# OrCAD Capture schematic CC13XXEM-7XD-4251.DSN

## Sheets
1 CC13xxEM-7XD-4251: size A3; title: CC13xxEM-7XD-4251, main; rev: 1.1.0
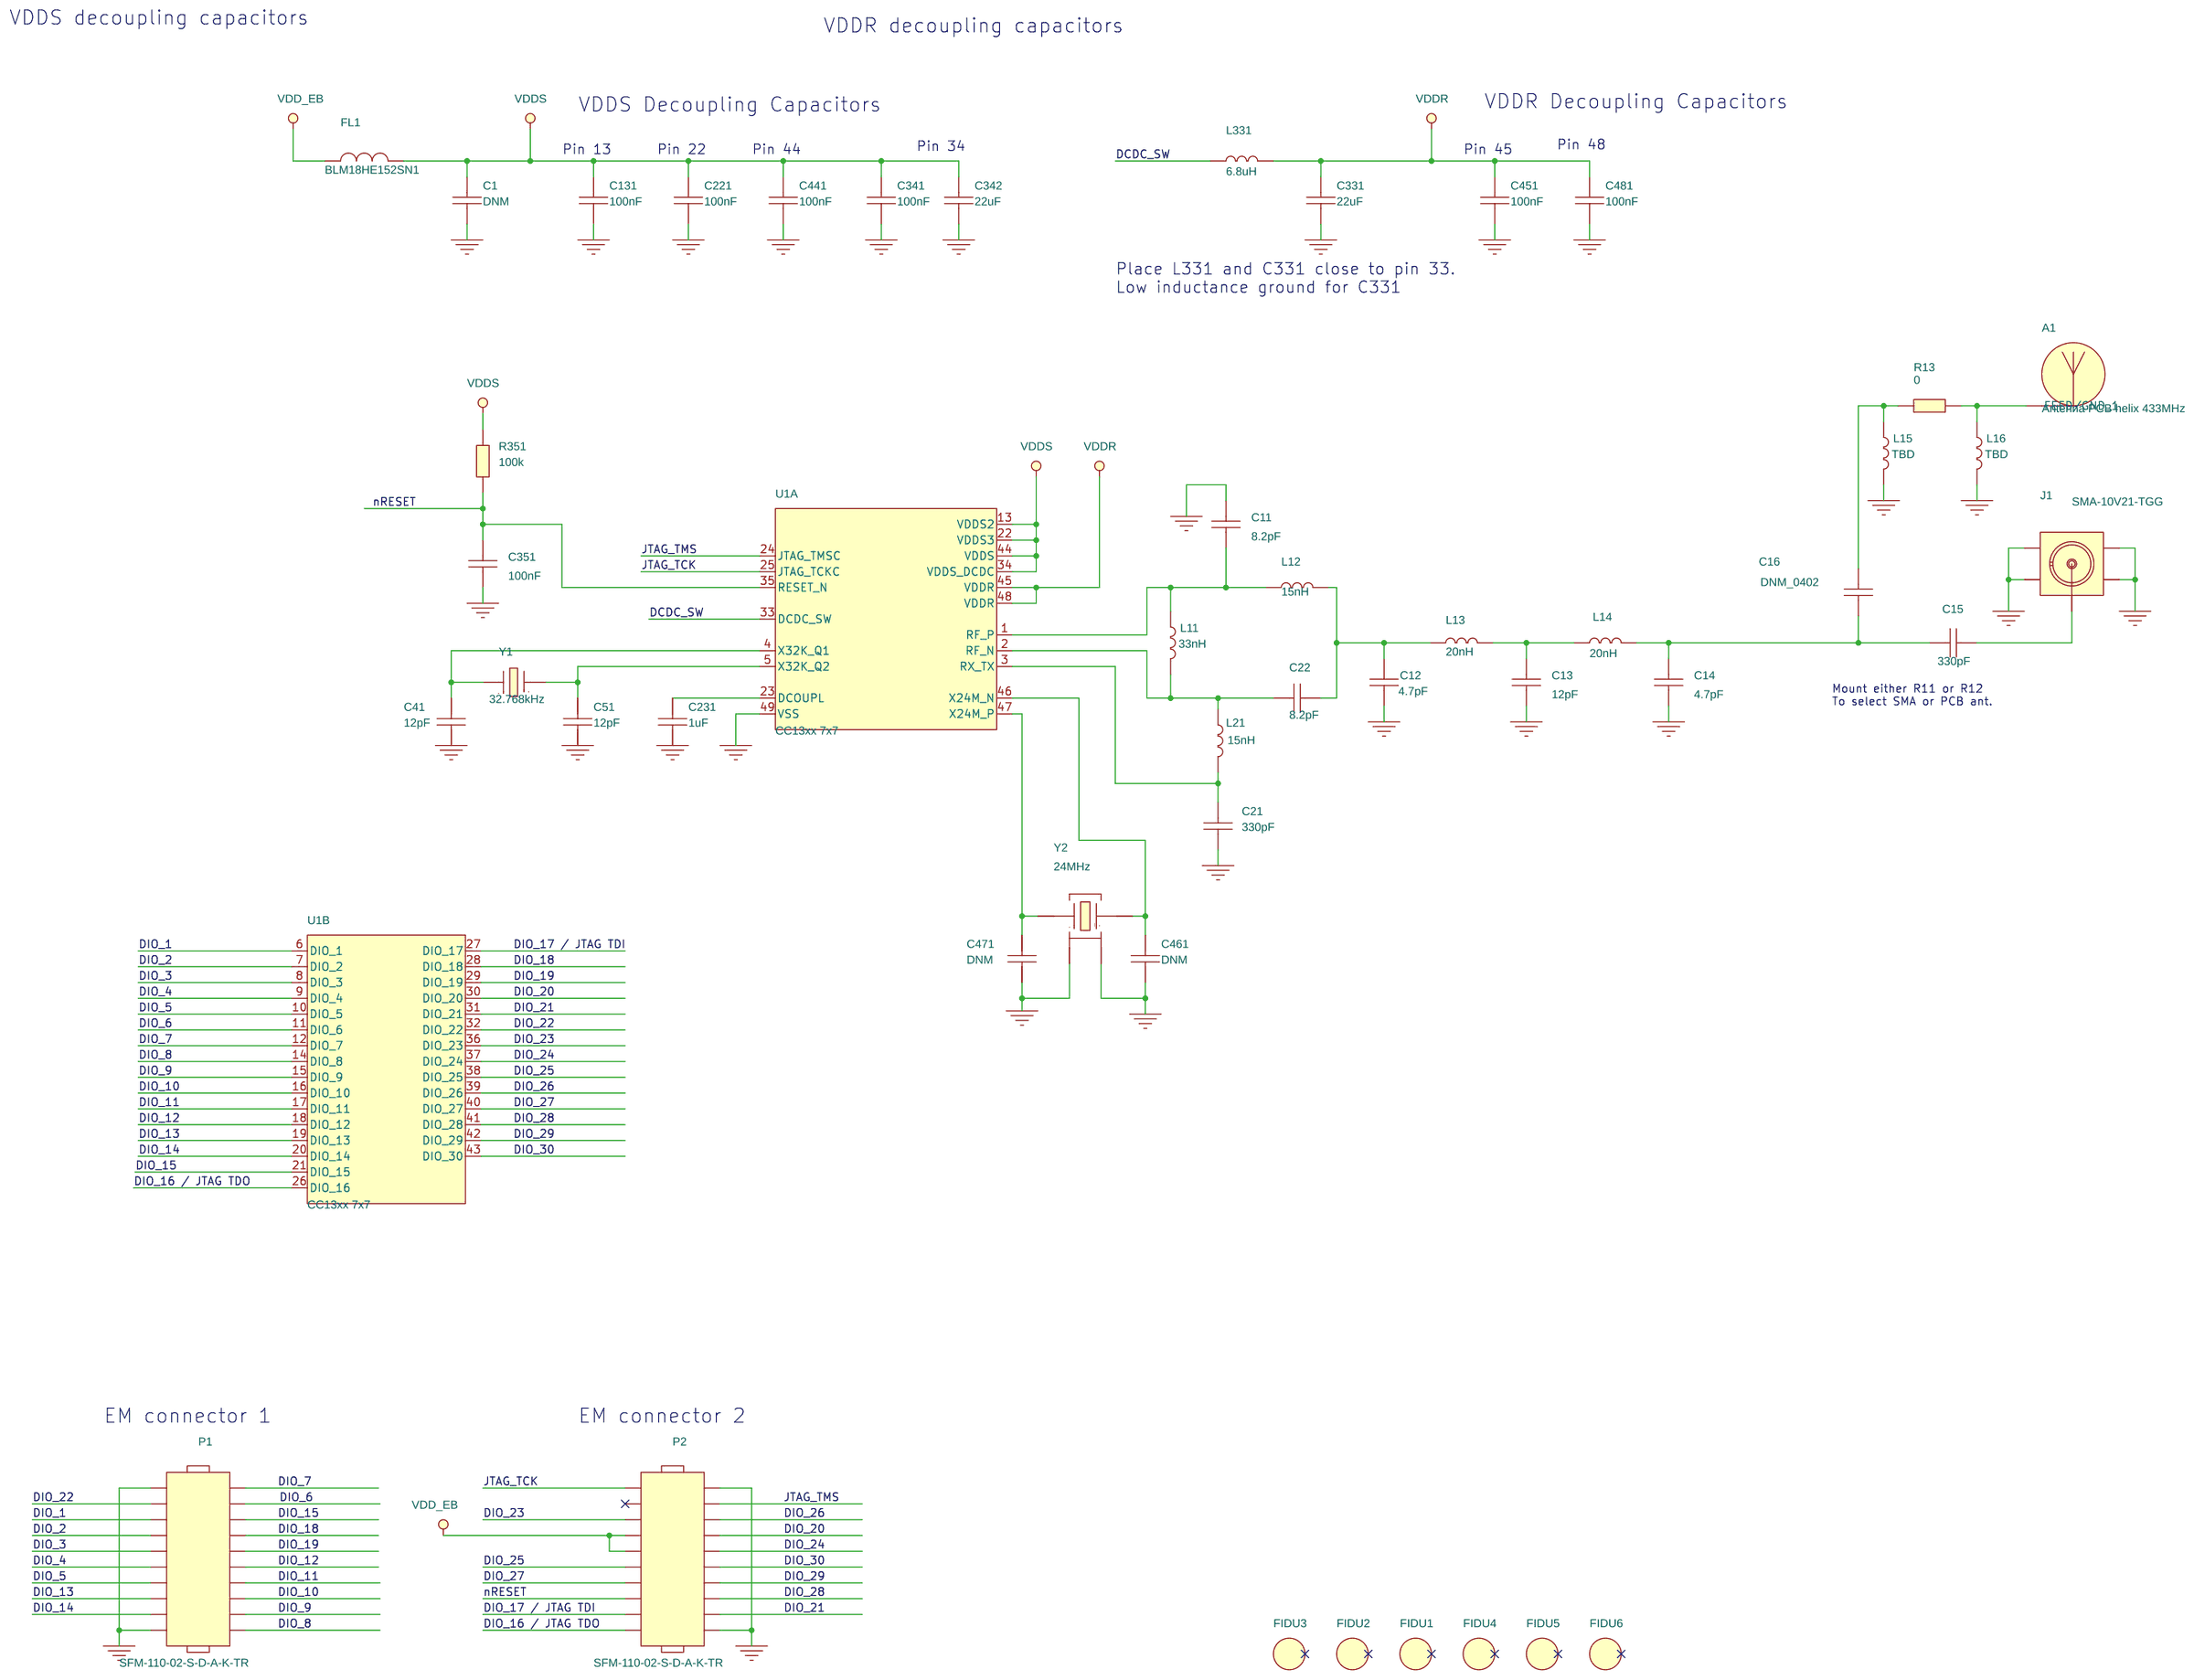
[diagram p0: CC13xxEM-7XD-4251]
2 Revision: title: CC13xxEM-7XD-4251, rev history
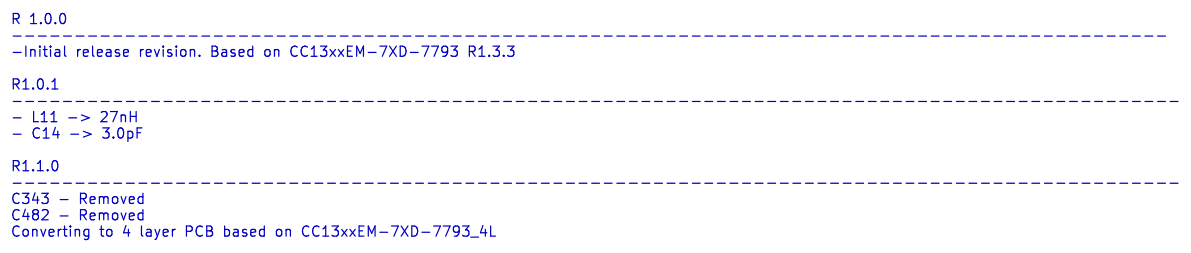
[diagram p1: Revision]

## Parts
A1  Antenna PCB helix 433MHz  [Antenna_433MHz_A2N]
C1  DNM  [CAPC1608X90L]
C11  8.2pF  [CAPC1005X60L]
C12  4.7pF  [CAPC1005X60L]
C13  12pF  [CAPC1005X60L]
C14  4.7pF  [CAPC1005X60L]
C15  330pF  [CAPC1005X60L]
C16  DNM_0402  [CAPC1005X60L]
C21  330pF  [CAPC1005X60L]
C22  8.2pF  [CAPC1005X60L]
C41  12pF  [CAPC1005X60L]
C51  12pF  [CAPC1005X60L]
C131  100nF  [CAPC1005X60L]
C221  100nF  [CAPC1005X60L]
C231  1uF  [CAPC1005X60L]
C331  22uF  [CAPC1608X100A2L]
C341  100nF  [CAPC1608X90L]
C342  22uF  [CAPC1608X100A2L]
C351  100nF  [CAPC1005X60L]
C441  100nF  [CAPC1005X60L]
C451  100nF  [CAPC1005X60L]
C461  DNM  [CAPC1005X60L]
C471  DNM  [CAPC1005X60L]
C481  100nF  [CAPC1005X60L]
FIDU1  FIDU_1MM  [FID100X115]
FIDU2  FIDU_1MM  [FID100X115]
FIDU3  FIDU_1MM  [FID100X115]
FIDU4  FIDU_1MM  [FID100X115]
FIDU5  FIDU_1MM  [FID100X115]
FIDU6  FIDU_1MM  [FID100X115]
FL1  BLM18HE152SN1  [FIL_BLM18HE152SN1DL]
J1  SMA-10V21-TGG  [HUSTSAN_SMA10V21TGGAN]
L11  33nH  [INDC1005X60L]
L12  15nH  [IND_LQW15AL]
L13  20nH  [IND_LQW15AL]
L14  20nH  [IND_LQW15AL]
L15  TBD  [INDC1005X60L]
L16  TBD  [INDC1005X60L]
L21  15nH  [IND_LQW15AL]
L331  6.8uH  [INDC2012X150L]
P1  SFM-110-02-S-D-A-K-TR  [SAMTEC_SFM11002AN]
P2  SFM-110-02-S-D-A-K-TR  [SAMTEC_SFM11002AN]
R13  0  [RESC1005X40L]
R351  100k  [RESC1005X40L]
U1  CC13xx 7x7  [QFNFC50P700X700X80-49CN]  (sections A,B)
Y1  32.768kHz  [XTAL_FC-135N]
Y2  24MHz  [OSCCC250X320X60-4L]

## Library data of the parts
A1 = ANTENNA: ANTENNA, NON COMPONENT, PCB HELIX 433MHz, NOT APPLY; AutoDoc File: http://notefied-dynamic-precision.com/DB/Apps/Desktop/Item/Object.aspx?id=87265; Budget Currency: N/A; Budget Price: N/A; Datasheet URL 1: N/A; Datasheet URL 2: www.ti.com; Definied Quality: COMMERCIAL; Esd Level: N/A; FPLIST: Antenna_433MHz_A2N,; Frequency: 433MHz; Last Time Buy: N/A; Lead Time: N/A; LifeCycle Status: ACTIVE; MPN: ANTENNA PCB HELIX 433MHz; MPN Status: ACTIVE; MSL: N/A; MTBF: N/A; MTBF Standard: N/A; Manufacturer: TEXAS INSTRUMENTS; Max Oper Temp: N/A; Min Oper Temp: N/A; Mounting Type: NOT APPLY; NOTE Status: PREFERRED; Packing Size: 2500; Packing Type: TAPE_&_REEL; Part Number: 13-00398; Part Type: MECHANIC\ANTENNA\NON_COMPONENT; Revision: R003; RoHS Status: ROHS_COMPLIANT; WEIGHT: N/A
C1 = CAPACITOR: CAPACITOR, DO NOT MOUNT, 0603, SMD; ALT_SYMBOLS: CAPC1608X90L,CAPC1608X90M; AutoDoc File: http://notefied-dynamic-precision.com/DB/Apps/Desktop/Item/Object.aspx?id=50475; FPLIST: CAPC1608X90N,CAPC1608X90L,CAPC1608X90M; Old Footprint: CAPC1608X90N,0603; Part Number: 02-01324; Part Type: CAPACITOR\CERAMIC\0603; Revision: R003
C11 C22 = CAPACITOR: CAPACITOR, CERAMIC C0G, 8.2pF, 50V, -0.25pF/+0.25pF, -55DEGC/+125DEGC, 0402, SMD; ALT_SYMBOLS: CAPC1005X60M,CAPC1005X60L; AutoDoc File: http://notefied-dynamic-precision.com/DB/Apps/Desktop/Item/Object.aspx?id=85864; Budget Currency: EUR; Budget Price: 0.007; Datasheet URL 1: http://search.murata.co.jp/Ceramy/image/img/w_hinm/L0005E.pdf; Datasheet URL 2: http://psearch.murata.com/capacitor/product/GRM1555C1H8R2CA01%23.pdf; Definied Quality: INDUSTRIAL; Dielectric Type: C0G/NP0; Esd Level: N/A; FPLIST: CAPC1005X60N,CAPC1005X60M,CAPC1005X60L; Last Time Buy: N/A; Lead Time: 12; LifeCycle Status: ACTIVE; MPN: GRM1555C1H8R2CA01D; MPN Status: ACTIVE; MSL: 1; MTBF: N/A; MTBF Standard: N/A; Manufacturer: MURATA; Max Oper Temp: +125DEGC; Max Tol: +0.25pF; Min Oper Temp: -55DEGC; Min Tol: -0.25pF; Mounting Type: SMD; NOTE Status: PREFERRED; Old Footprint: CAPC1005X60N; PCB Package: 0402; Packing Size: 10000; Packing Type: TAPE_&_REEL; Part Number: 02-04322; Part Type: CAPACITOR\CERAMIC\0402\STANDARD; Revision: R001; RoHS Status: ROHS_COMPLIANT; Rtd Voltage: 50V; WEIGHT: 0.0016g
C12 C14 = CAPACITOR: CAPACITOR, CERAMIC C0G/NP0, 4.7pF, 50V, -0.25pF/+0.25pF, -55DEGC/+125DEGC, 0402, SMD; ALT_SYMBOLS: CAPC1005X60L,CAPC1005X60M; AutoDoc File: http://notefied-dynamic-precision.com/DB/Apps/Desktop/Item/Object.aspx?id=96812; Budget Currency: EUR; Budget Price: 0.006; Datasheet URL 1: N/A; Datasheet URL 2: http://psearch.murata.com/capacitor/product/GRM1555C1H4R7CA01%23.pdf; Definied Quality: INDUSTRIAL; Dielectric Type: C0G/NP0; Esd Level: N/A; FPLIST: CAPC1005X60N,CAPC1005X60L,CAPC1005X60M; Last Time Buy: N/A; Lead Time: 18; LifeCycle Status: ACTIVE; MPN: GRM1555C1H4R7CA01D; MPN Status: ACTIVE; MSL: N/A; MTBF: N/A; MTBF Standard: N/A; Manufacturer: MURATA; Max Oper Temp: +125DEGC; Max Tol: +0.25pF; Min Oper Temp: -55DEGC; Min Tol: -0.25pF; Mounting Type: SMD; NOTE Status: PREFERRED; Old Footprint: CAPC1005X60N; PCB Package: 0402; Packing Size: 10000; Packing Type: TAPE_&_REEL; Part Number: 02-06094; Part Type: CAPACITOR\CERAMIC\0402\STANDARD; Revision: R001; RoHS Status: ROHS_COMPLIANT; Rtd Voltage: 50V; WEIGHT: 0.0016g
C13 = CAPACITOR: CAPACITOR, CERAMIC C0G/NP0, 12pF, 50V, -5%/+5%, -55DEGC/+125DEGC, 0402, SMD; ALT_SYMBOLS: CAPC1005X60L,CAPC1005X60M; AutoDoc File: http://notefied-dynamic-precision.com/DB/Apps/Desktop/Item/Object.aspx?id=84867; Budget Currency: EUR; Budget Price: 0.007; Datasheet URL 1: http://search.murata.co.jp/Ceramy/image/img/w_hinm/L0005E.pdf; Datasheet URL 2: http://psearch.murata.com/capacitor/product/GRM1555C1H120JA01%23.pdf; Definied Quality: INDUSTRIAL; Dielectric Type: C0G/NP0; Esd Level: N/A; FPLIST: CAPC1005X60N,CAPC1005X60L,CAPC1005X60M; Last Time Buy: N/A; Lead Time: 12; LifeCycle Status: ACTIVE; MPN: GRM1555C1H120JA01D; MPN Status: ACTIVE; MSL: 1; MTBF: N/A; MTBF Standard: N/A; Manufacturer: MURATA; Max Oper Temp: +125DEGC; Max Tol: +5%; Min Oper Temp: -55DEGC; Min Tol: -5%; Mounting Type: SMD; NOTE Status: PREFERRED; Old Footprint: CAPC1005X60N; PCB Package: 0402; Packing Size: 10000; Packing Type: TAPE_&_REEL; Part Number: 02-04168; Part Type: CAPACITOR\CERAMIC\0402\STANDARD; Revision: R000; RoHS Status: ROHS_COMPLIANT; Rtd Voltage: 50V; WEIGHT: 0.0016g
C15 C21 = CAPACITOR: CAPACITOR, CERAMIC C0G/NP0, 330pF, 50V, -5%/+5%, -55DEGC/+125DEGC, 0402, SMD; ALT_SYMBOLS: CAPC1005X60L,CAPC1005X60M; AutoDoc File: http://notefied-dynamic-precision.com/DB/Apps/Desktop/Item/Object.aspx?id=71365; Budget Currency: EUR; Budget Price: 0.017; Datasheet URL 1: http://search.murata.co.jp/Ceramy/image/img/w_hinm/L0005E.pdf; Datasheet URL 2: http://psearch.murata.com/capacitor/product/GRM1555C1H331JA01%23.pdf; Definied Quality: INDUSTRIAL; Dielectric Type: C0G/NP0; Esd Level: N/A; FPLIST: CAPC1005X60N,CAPC1005X60L,CAPC1005X60M; Last Time Buy: N/A; Lead Time: 16; LifeCycle Status: ACTIVE; MPN: GRM1555C1H331JA01D; MPN Status: ACTIVE; MSL: 1; MTBF: N/A; MTBF Standard: N/A; Manufacturer: MURATA; Max Oper Temp: +125DEGC; Max Tol: +5%; Min Oper Temp: -55DEGC; Min Tol: -5%; Mounting Type: SMD; NOTE Status: PREFERRED; Old Footprint: CAPC1005X60N,0402; PCB Package: 0402; Packing Size: 10000; Packing Type: TAPE_&_REEL; Part Number: 02-01637; Part Type: CAPACITOR\CERAMIC\0402\STANDARD; Revision: R001; RoHS Status: ROHS_COMPLIANT; Rtd Voltage: 50V; WEIGHT: 0.0016g
C16 = CAPACITOR: CAPACITOR, CERAMIC, TBD, -55DEGC/+125DEGC, 0402, DNM, SMD; ALT_SYMBOLS: CAPC1005X60L,CAPC1005X60M; AutoDoc File: http://notefied-dynamic-precision.com/DB/Apps/Desktop/Item/Object.aspx?id=84862; Budget Currency: USD; Budget Price: 0.00589; Datasheet URL 1: N/A; Datasheet URL 2: N/A; Definied Quality: INDUSTRIAL; Dielectric Type: MISSING-INFO; Esd Level: N/A; FPLIST: CAPC1005X60N,CAPC1005X60L,CAPC1005X60M; Last Time Buy: N/A; Lead Time: N/A; LifeCycle Status: ACTIVE; MPN: CAPACITOR_0402_DNM_N/A_M; MPN Status: ACTIVE; MSL: N/A; MTBF: N/A; MTBF Standard: N/A; Manufacturer: MANUFACTURER SELECTION; Max Oper Temp: +125DEGC; Min Oper Temp: -55DEGC; Mounting Type: SMD; NOTE Status: PREFERRED; Old Footprint: CAPC1005X60N; PCB Package: 0402; Packing Size: 10000; Packing Type: TAPE_&_REEL; Part Number: 02-04164; Part Type: CAPACITOR\CERAMIC\0402\STANDARD; Revision: R000; RoHS Status: MISSING_INFO; WEIGHT: N/A
C41 C51 = CAPACITOR: CAPACITOR, CERAMIC C0G/NP0, 12pF, 50V, -5%/+5%, -55DEGC/+125DEGC, 0402, SMD; ALT_SYMBOLS: CAPC1005X60L,CAPC1005X60M; AutoDoc File: http://notefied-dynamic-precision.com/DB/Apps/Desktop/Item/Object.aspx?id=84867; Budget Currency: EUR; Budget Price: 0.006; Datasheet URL 1: http://search.murata.co.jp/Ceramy/image/img/w_hinm/L0005E.pdf; Datasheet URL 2: http://psearch.murata.com/capacitor/product/GRM1555C1H120JA01%23.pdf; Definied Quality: INDUSTRIAL; Dielectric Type: C0G/NP0; Esd Level: N/A; FPLIST: CAPC1005X60N,CAPC1005X60L,CAPC1005X60M; Last Time Buy: N/A; Lead Time: 12; MPN: GRM1555C1H120JA01D; MPN Status: ACTIVE; MSL: 1; MTBF: N/A; MTBF Standard: N/A; Manufacturer: MURATA; Max Oper Temp: +125DEGC; Max TC: +30PPM/DEGC; Max Tol: +5%; Min Oper Temp: -55DEGC; Min TC: -30PPM/DEGC; Min Tol: -5%; Mounting Type: SMD; NOTE Status: PREFERRED; Old Footprint: CAPC1005X60N; PCB Package: 0402; Packing Size: 10000; Packing Type: TAPE_&_REEL; Part Number: 02-04168; Part Type: CAPACITOR\CERAMIC\0402; Revision: R000; RoHS Status: ROHS_COMPLIANT; Rtd Voltage: 50V; WEIGHT: 0.0016g
C131 C221 C351 C441 C451 C481 = CAPACITOR: CAPACITOR, CERAMIC X7R, 100nF, 6.3V, -10%/+10%, -55DEGC/+125DEGC, 0402, SMD; ALT_SYMBOLS: CAPC1005X60L,CAPC1005X60M; AutoDoc File: http://notefied-dynamic-precision.com/DB/Apps/Desktop/Item/Object.aspx?id=73748; Budget Currency: EUR; Budget Price: 0.003; Datasheet URL 1: http://search.murata.co.jp/Ceramy/image/img/A01X/G101/ENG/GRM155R70J104KA01-01.pdf; Datasheet URL 2: http://search.murata.co.jp/Ceramy/image/img/A01X/G101/ENG/GRM155R70J104KA01-01.pdf; Dielectric Type: X7R; FPLIST: CAPC1005X60N,CAPC1005X60L,CAPC1005X60M; Lead Time: 10; LifeCycle Status: ACTIVE; MPN: GRM155R70J104KA01D; MPN Status: ACTIVE; Manufacturer: MURATA; Max Oper Temp: +125DEGC; Max Tol: +10%; Min Oper Temp: -55DEGC; Min Tol: -10%; Mounting Type: SMD; NOTE Status: PREFERRED; Old Footprint: CAPC1005X60N,0402; PCB Package: 0402; Packing Size: 10000; Packing Type: TAPE_&_REEL; Part Number: 02-02323; Part Type: CAPACITOR\CERAMIC\0402; Revision: R000; RoHS Status: ROHS_COMPLIANT; Rtd Voltage: 6.3V; WEIGHT: 0.0016g
C231 = CAPACITOR: CAPACITOR, CERAMIC X5R, 1uF, 10V, -10%/+10%, -55DEGC/+85DEGC, 0402, SMD; ALT_SYMBOLS: CAPC1005X60L,CAPC1005X60M; AutoDoc File: http://notefied-dynamic-precision.com/DB/Apps/Desktop/Item/Object.aspx?id=74236; Budget Currency: EUR; Budget Price: 0.015; Datasheet URL 1: http://search.murata.co.jp/Ceramy/image/img/w_hinm/L0005E.pdf; Datasheet URL 2: http://psearch.murata.com/capacitor/product/GRM155R61A105KE15%23.pdf; Definied Quality: INDUSTRIAL; Dielectric Type: X5R; Esd Level: N/A; FPLIST: CAPC1005X60N,CAPC1005X60L,CAPC1005X60M; Last Time Buy: N/A; Lead Time: 14; MPN: GRM155R61A105KE15D; MPN Status: ACTIVE; MSL: 1; MTBF: N/A; MTBF Standard: N/A; Manufacturer: MURATA; Max Oper Temp: +85DEGC; Max Tol: +10%; Min Oper Temp: -55DEGC; Min Tol: -10%; Mounting Type: SMD; NOTE Status: PREFERRED; Old Footprint: CAPC1005X60N,0402; PCB Package: 0402; Packing Size: 10000; Packing Type: TAPE_&_REEL; Part Number: 02-02381; Part Type: CAPACITOR\CERAMIC\0402; Revision: R002; RoHS Status: ROHS_COMPLIANT; Rtd Voltage: 10V; WEIGHT: 0.0016g
C331 C342 = CAPACITOR: CAPACITOR, CERAMIC, X5R, 22uF, 6.3V, -20%/+20%, -55DEGC/+85DEGC, 0603, SMD; ALT_SYMBOLS: CAPC1608X100A2L,CAPC1608X100A2M; AutoDoc File: http://notefied-dynamic-precision.com/DB/Apps/Desktop/Item/Object.aspx?id=104385; Budget Currency: USD; Budget Price: 0.045; Datasheet URL 1: N/A; Datasheet URL 2: http://psearch.en.murata.com/capacitor/product/GRM188R60J226MEA0%23.pdf; Definied Quality: INDUSTRIAL; Dielectric Type: X5R; Esd Level: N/A; FPLIST: CAPC1608X100A2N,CAPC1608X100A2L,CAPC1608X100A2M; Last Time Buy: N/A; Lead Time: 26; LifeCycle Status: ACTIVE; MPN: GRM188R60J226MEA0D; MPN Status: ACTIVE; Manufacturer: MURATA; Max Oper Temp: +85DEGC; Max Tol: +20%; Min Oper Temp: -55DEGC; Min Tol: -20%; Mounting Type: SMD; NOTE Status: PREFERRED; Old Footprint: CAPC1608X100A2N; PCB Package: 0603; Packing Size: 4000; Packing Type: TAPE_&_REEL; Part Number: 02-07053; Part Type: CAPACITOR\CERAMIC\0603; Revision: R001; RoHS Status: ROHS_COMPLIANT; Rtd Voltage: 6.3V; WEIGHT: 0.0091g
C341 = CAPACITOR: CAPACITOR, CERAMIC X7R, 100nF, 25V, -10%/+10%, -55DEGC/+125DEGC, 0603, SMD; ALT_SYMBOLS: CAPC1608X90L,CAPC1608X90M; AutoDoc File: http://notefied-dynamic-precision.com/DB/Apps/Desktop/Item/Object.aspx?id=72070; Budget Currency: EUR; Budget Price: 0.006; Cage Code: C0151; Datasheet URL 1: http://search.murata.co.jp/Ceramy/image/img/w_hinm/L0005E.pdf; Datasheet URL 2: http://psearch.murata.com/capacitor/product/GRM188R71E104KA01%23.pdf; Definied Quality: INDUSTRIAL; Dielectric Type: X7R; Esd Level: N/A; FPLIST: CAPC1608X90N,CAPC1608X90L,CAPC1608X90M; Last Time Buy: N/A; Lead Time: 10; MPN: GRM188R71E104KA01D; MPN Status: NRND; MSL: 1; MTBF: N/A; MTBF Standard: N/A; Manufacturer: MURATA; Max Oper Temp: +125DEGC; Max Tol: +10%; Min Oper Temp: -55DEGC; Min Tol: -10%; Mounting Type: SMD; NOTE Status: PREFERRED; Old Footprint: CAPC1608X90N,0603; PCB Package: 0603; Packing Size: 4000; Packing Type: TAPE_&_REEL; Part Number: 02-01992; Part Type: CAPACITOR\CERAMIC\0603; Revision: R001; RoHS Status: ROHS_COMPLIANT; Rtd Voltage: 25V; WEIGHT: 0.0063g
C461 C471 = CAPACITOR: CAPACITOR, CERAMIC, N/A VALUE, -55DEGC/+125DEGC, 0402, SMD; ALT_SYMBOLS: CAPC1005X60L,CAPC1005X60M; AutoDoc File: http://notefied-dynamic-precision.com/DB/Apps/Desktop/Item/Object.aspx?id=84862; Budget Currency: USD; Budget Price: 0.00589; FPLIST: CAPC1005X60N,CAPC1005X60L,CAPC1005X60M; MPN: CAPACITOR_0402_DNM_N/A_M; MPN Status: ACTIVE; Manufacturer: Manufacturer selection; Max Oper Temp: +125DEGC; Min Oper Temp: -55DEGC; Mounting Type: SMD; NOTE Status: PREFERRED; Old Footprint: CAPC1005X60N; PCB Package: 0402; Packing Size: 10000; Packing Type: TAPE_&_REEL; Part Number: 02-04164; Part Type: CAPACITOR\CERAMIC\0402; Revision: R000; RoHS Status: PART NOT KNOWN
FIDU1-FIDU6 = FIDMARK: FIDUCIAL MARK, ROUND 1MM; AutoDoc File: http://notefied-dynamic-precision.com/DB/Apps/Desktop/Item/Object.aspx?id=74548; Part Number: 19-00111; Part Type: NON_COMPONENT\FIDUCIAL; Revision: R001
FL1 = FILTER_2PIN: FILTER, EMI, 1500@100MHz, -55DEGC/+125DEGC, 0603, SMD; ALT_SYMBOLS: FIL_BLM18HE152SN1DL,FIL_BLM18HE152SN1DM; AutoDoc File: http://notefied-dynamic-precision.com/DB/Apps/Desktop/Item/Object.aspx?id=85575; Budget Currency: EUR; Budget Price: 0.085; Datasheet URL 1: http://search.murata.co.jp/Ceramy/image/img/PDF/ENG/L0110S0101BLM18H.pdf; Datasheet URL 2: http://search.murata.co.jp/Ceramy/image/img/PDF/ENG/L0110S0101BLM18H.pdf; FPLIST: FIL_BLM18HE152SN1DN,FIL_BLM18HE152SN1DL,FIL_BLM18HE152SN1DM; Impedance: 1500@100MHz; Lead Time: 26; MPN: BLM18HE152SN1D; MPN Status: ACTIVE; Manufacturer: MURATA; Max Oper Temp: +125DEGC; Max Tol: +25%; Min Oper Temp: -55DEGC; Min Tol: -25%; Mounting Type: SMD; NOTE Status: PREFERRED; Old Footprint: FIL_BLM18HE152SN1DN; PCB Package: 0603; Packing Size: 4000; Packing Type: TAPE_&_REEL; Part Number: 04-00470; Part Type: FILTER\EMI\0603; Revision: R001; RoHS Status: ROHS_COMPLIANT; Rtd Current: 0.5A; WEIGHT: 0.006g
J1 = CONN_COAX_1+4: CONNECTOR, COAX RF, STRAIGHT, FEMALE, 1 PIN, SMD; ALT_SYMBOLS: HUSTSAN_SMA10V21TGGL,HUSTSAN_SMA10V21TGGM; AutoDoc File: http://notefied-dynamic-precision.com/DB/Apps/Desktop/Item/Object.aspx?id=84956; Budget Currency: USD; Budget Price: 1.21; Datasheet URL 1: http://www.hustsan.com.tw/uploaddir/product/SMA-10V21.pdf; Datasheet URL 2: http://www.hustsan.com.tw/uploaddir/product/SMA-10V21.pdf; FPLIST: HUSTSAN_SMA10V21TGGAN,HUSTSAN_SMA10V21TGGN; Lead Time: 5; MPN Status: ACTIVE; MSL: N/A; Manufacturer: HUS-TSAN; Mounting Type: SMD; NOTE Status: PREFERRED; No Of Pos: 1; Old Footprint: HUSTSAN_SMA10V21TGGAN,HUSTSAN_SMA10V21TGGN; Packing Size: 350; Packing Type: TAPE_&_REEL; Part Number: 06-02188; Part Type: CONNECTOR\COAX; Revision: R003; RoHS Status: N/A; WEIGHT: N/A
L11 = INDUCTOR: INDUCTOR, RF, CHIP, NON-MAGNETIC CORE, 33nH, -5%/+5%, 0.26A, -55DEGC/+125DEGC, 0402, SMD; ALT_SYMBOLS: INDC1005X60L,INDC1005X60M; AutoDoc File: http://notefied-dynamic-precision.com/DB/Apps/Desktop/Item/Object.aspx?id=71316; Budget Currency: N/A; Budget Price: N/A; Datasheet URL 1: N/A; Datasheet URL 2: http://psearch.murata.com/inductor/product/LQW15AN33NJ00%23.pdf; Definied Quality: INDUSTRIAL; Esd Level: N/A; FPLIST: INDC1005X60N,INDC1005X60L,INDC1005X60M; Last Time Buy: N/A; Lead Time: N/A; LifeCycle Status: ACTIVE; MPN: LQW15AN33NJ00B; MPN Status: ACTIVE; MSL: N/A; MTBF: N/A; MTBF Standard: N/A; Manufacturer: MURATA; Max Oper Temp: +125DEGC; Max Tol: +5%; Min Oper Temp: -55DEGC; Min Tol: -5%; Mounting Type: SMD; NOTE Status: PREFERRED; Old Footprint: INDC1005X60N; PCB Package: 0402; Packing Size: 500; Packing Type: BULK; Part Number: 03-06141; Part Type: INDUCTOR\RF\CHIP\0402; Revision: R000; RoHS Status: ROHS_COMPLIANT; Rtd Current: 0.26A; WEIGHT: 0.0008g
L12 L21 = INDUCTOR: INDUCTOR, RF, CHIP, NON-MAGNETIC CORE, 15nH, -5%/+5%, 0.46A, -55DEGC/+125DEGC, 0402, SMD; ALT_SYMBOLS: IND_LQW15AM,IND_LQW15AL; AutoDoc File: http://notefied-dynamic-precision.com/DB/Apps/Desktop/Item/Object.aspx?id=86087; Budget Currency: EUR; Budget Price: 0.144; Datasheet URL 1: N/A; Datasheet URL 2: http://psearch.murata.com/inductor/product/LQW15AN15NJ00%23.pdf; Definied Quality: INDUSTRIAL; Esd Level: N/A; FPLIST: IND_LQW15AN,IND_LQW15AM,IND_LQW15AL; Frequency: 5GHz; Last Time Buy: N/A; Lead Time: 9; LifeCycle Status: ACTIVE; MPN: LQW15AN15NJ00D; MPN Status: ACTIVE; MSL: N/A; MTBF: N/A; MTBF Standard: N/A; Manufacturer: MURATA; Max Oper Temp: +125DEGC; Max Tol: +5%; Min Oper Temp: -55DEGC; Min Tol: -5%; Mounting Type: SMD; NOTE Status: PREFERRED; Old Footprint: IND_LQW15AN; PCB Package: 0402; Packing Size: 10000; Packing Type: TAPE_&_REEL; Part Number: 03-06555; Part Type: INDUCTOR\RF\CHIP\0402; Resistance: 0.16; Revision: R001; RoHS Status: ROHS_COMPLIANT; Rtd Current: 0.46A; WEIGHT: 0.0008g
L13 L14 = INDUCTOR: INDUCTOR, RF, CHIP, NON-MAGNETIC CORE, 20nH, -5%/+5%, 0.37A, -55DEGC/+125DEGC, 0402, SMD; ALT_SYMBOLS: IND_LQW15AL,IND_LQW15AM; AutoDoc File: http://notefied-dynamic-precision.com/DB/Apps/Desktop/Item/Object.aspx?id=97240; Budget Currency: EUR; Budget Price: 0.144; Datasheet URL 1: N/A; Datasheet URL 2: http://psearch.murata.com/inductor/product/LQW15AN20NJ00%23.pdf; Definied Quality: INDUSTRIAL; Esd Level: N/A; FPLIST: IND_LQW15AN,IND_LQW15AL,IND_LQW15AM; Frequency: 4GHz; Last Time Buy: N/A; Lead Time: 9; LifeCycle Status: ACTIVE; MPN: LQW15AN20NJ00D; MPN Status: ACTIVE; MSL: N/A; MTBF: N/A; MTBF Standard: N/A; Manufacturer: MURATA; Max Oper Temp: +125DEGC; Max Tol: +5%; Min Oper Temp: -55DEGC; Min Tol: -5%; Mounting Type: SMD; NOTE Status: PREFERRED; Old Footprint: IND_LQW15AN; PCB Package: 0402; Packing Size: 10000; Packing Type: TAPE_&_REEL; Part Number: 03-06992; Part Type: INDUCTOR\RF\CHIP\0402; Resistance: 0.27; Revision: R001; RoHS Status: ROHS_COMPLIANT; Rtd Current: 0.37A; WEIGHT: 0.0008g
L15 L16 = INDUCTOR: INDUCTOR, TO BE DECIDED, 0402, SMD; ALT_SYMBOLS: INDC1005X60M,INDC1005X60L; AutoDoc File: http://notefied-dynamic-precision.com/DB/Apps/Desktop/Item/Object.aspx?id=45714; Budget Currency: N/A; Budget Price: N/A; Datasheet URL 1: N/A; Datasheet URL 2: N/A; Definied Quality: COMMERCIAL; Esd Level: N/A; FPLIST: INDC1005X60N,INDC1005X60M,INDC1005X60L; Last Time Buy: N/A; Lead Time: N/A; LifeCycle Status: ACTIVE; MPN: IND_TBD_0402; MPN Status: ACTIVE; MSL: N/A; MTBF: N/A; MTBF Standard: N/A; Manufacturer: MANUFACTURER SELECTION; Mounting Type: SMD; NOTE Status: PREFERRED; Old Footprint: 0402; Packing Size: N/A; Packing Type: N/A; Part Number: 03-01022; Part Type: INDUCTOR\CHIP\0402; Revision: R002; RoHS Status: ROHS_COMPLIANT; WEIGHT: N/A
L331 = INDUCTOR: INDUCTOR, CHIP, FERRITE CORE, 6.8uH, -20%/+20%, IR:1.1A, -55DEGC/+125DEGC, 0805, SMD; ALT_SYMBOLS: INDC2012X150L,INDC2012X150M; AutoDoc File: http://notefied-dynamic-precision.com/DB/Apps/Desktop/Item/Object.aspx?id=102853; Datasheet URL 1: N/A; Datasheet URL 2: http://product.tdk.com/inductor/ind/detailed_information.php?lang=en&ref=us&part_no=MLZ2012N6R8LT000; FPLIST: INDC2012X150N,INDC2012X150L,INDC2012X150M; MPN: MLZ2012N6R8LT000; MPN Status: ACTIVE; Manufacturer: TDK; Max Oper Temp: +125DEGC; Max Tol: +20%; Min Oper Temp: -55DEGC; Min Tol: -20%; Mounting Type: SMD; NOTE Status: PREFERRED; Old Footprint: INDC2012X150N; PCB Package: 0805; Packing Size: 4000; Packing Type: TAPE_&_REEL; Part Number: 03-07266; Part Type: INDUCTOR\CHIP\0805; Resistance: 0.25; Revision: R001; RoHS Status: ROHS_COMPLIANT; Rtd Current: 1.1A; WEIGHT: 0.01g
P1 P2 = CONN_HEADER_2X10_P_S: CONNECTOR, HEADER, FEMALE, STRAIGHT, 2 ROWS, 20 PINS, PITCH 1.27mm, SMD; Alt IPC Footprints: SAMTEC_SFM11002AL,SAMTEC_SFM11002AM; AutoDoc File: https://notefied-dynamic-precision.com/NotefiedWebServices/AutoDocs.aspx?itemid=85603; Datasheet URL 1: http://www.samtec.com/ProductInformation/TechnicalSpecifications/CatalogPages.aspx?series=SFM; Datasheet URL 2: http://www.samtec.com/documents/webfiles/cpdf/SFM-1XX-XX-XX-S-XX-MKT1.pdf; MPN: SFM-110-02-SM-D-A-K-TR; MPN Status: ACTIVE; Manufacturer: SAMTEC; Max Oper Temp: +125DEGC; Min Oper Temp: -55DEGC; Mounting Type: SMD; NOTE Status: PREFERRED; No Of Pos: 20; No Of Rows: 2; Packing Size: 125; Packing Type: TAPE_&_REEL; Part Number: 06-02251; Part Type: CONNECTOR\HEADER; Pitch: 1.27mm; Revision: R001; RoHS Status: ROHS_COMPLIANT
R13 = RESISTOR: RESISTOR, THICK FILM, 0, -5%/+5%, 0.063W, 50V, -55DEGC/+155DEGC, 0402, SMD; ALT_SYMBOLS: RESC1005X40L,RESC1005X40M; AutoDoc File: http://notefied-dynamic-precision.com/DB/Apps/Desktop/Item/Object.aspx?id=75642; Budget Currency: USD; Budget Price: 0.00244; Datasheet URL 1: N/A; Datasheet URL 2: N/A; Definied Quality: INDUSTRIAL; Esd Level: N/A; FPLIST: RESC1005X40N,RESC1005X40L,RESC1005X40M; Last Time Buy: N/A; Lead Time: N/A; LifeCycle Status: ACTIVE; MPN: RESISTOR_0402_0_+/-5%_50V_0.063W_M_+/-200PPM; MPN Status: ACTIVE; MSL: N/A; MTBF: N/A; MTBF Standard: N/A; Manufacturer: MANUFACTURER SELECTION; Max Oper Temp: +155DEGC; Max TC: +200PPM/DEGC; Max Tol: +5%; Min Oper Temp: -55DEGC; Min TC: -200PPM/DEGC; Min Tol: -5%; Mounting Type: SMD; NOTE Status: PREFERRED; Old Footprint: RESC1005X40N; PCB Package: 0402; Packing Size: 10000; Packing Type: TAPE_&_REEL; Part Number: 01-11587; Part Type: RESISTOR\0402; Resistor Type: THICK FILM; Revision: R001; RoHS Status: ROHS_COMPLIANT; Rtd Power: 0.063W; Rtd Voltage: 50V; WEIGHT: N/A
R351 = RESISTOR: RESISTOR, THICK FILM, 100k, -1%/+1%, 0.063W, 50V, -55DEGC/+155DEGC, 0402, SMD; ALT_SYMBOLS: RESC1005X40L,RESC1005X40M; AutoDoc File: http://notefied-dynamic-precision.com/DB/Apps/Desktop/Item/Object.aspx?id=76892; Budget Currency: USD; Budget Price: 0.00244; Datasheet URL 1: N/A; Datasheet URL 2: N/A; Definied Quality: INDUSTRIAL; Esd Level: N/A; FPLIST: RESC1005X40N,RESC1005X40L,RESC1005X40M; Last Time Buy: N/A; Lead Time: N/A; LifeCycle Status: ACTIVE; MPN: RESISTOR_0402_100k_+/-1%_50V_0.063W_M_+/-100PPM; MPN Status: ACTIVE; MSL: N/A; MTBF: N/A; MTBF Standard: N/A; Manufacturer: MANUFACTURER SELECTION; Max Oper Temp: +155DEGC; Max TC: +100PPM/DEGC; Max Tol: +1%; Min Oper Temp: -55DEGC; Min TC: -100PPM/DEGC; Min Tol: -1%; Mounting Type: SMD; NOTE Status: PREFERRED; Old Footprint: RESC1005X40N; PCB Package: 0402; Packing Size: 10000; Packing Type: TAPE_&_REEL; Part Number: 01-12837; Part Type: RESISTOR\0402\PRECISION; Resistor Type: THICK FILM; Revision: R002; RoHS Status: ROHS_COMPLIANT; Rtd Power: 0.063W; Rtd Voltage: 50V; WEIGHT: N/A
U1 = IC_RF_CC13XX_7X7_QFN48_V2: IC, DIGITAL, CUSTOM, CC13xx 7x7, QFN48, SMD; ALT_SYMBOLS: QFNFC50P700X700X80-49CL,QFNFC50P700X700X80-49CM; AutoDoc File: http://notefied-dynamic-precision.com/DB/Apps/Desktop/Item/Object.aspx?id=90625; Budget Currency: N/A; Budget Price: N/A; Datasheet URL 1: N/A; Datasheet URL 2: www.ti.com; Definied Quality: COMMERCIAL; Esd Level: N/A; FPLIST: QFNFC50P700X700X80-49CN,QFNFC50P700X700X80-49CL,QFNFC50P700X700X80-49CM; Last Time Buy: N/A; Lead Time: N/A; MPN Status: ACTIVE; MSL: N/A; MTBF: N/A; MTBF Standard: N/A; Manufacturer: TEXAS INSTRUMENTS; Max Oper Temp: N/A; Min Oper Temp: N/A; Mounting Type: SMD; NOTE Status: PREFERRED; PCB Package: QFN48; Packing Size: N/A; Packing Type: N/A; Part Number: 18-28964; Part Type: IC\DIGITAL\OTHER; Revision: R003; RoHS Status: PART NOT KNOWN; Rtd Voltage: N/A; WEIGHT: N/A
Y1 = CRYSTAL: CRYSTAL, RESONATOR, 32.768kHz, -20PPM/+20PPM, -40DEGC/+85DEGC, SMD; ALT_SYMBOLS: XTAL_FC-135L,XTAL_FC-135M; AutoDoc File: http://notefied-dynamic-precision.com/DB/Apps/Desktop/Item/Object.aspx?id=91966; Budget Currency: USD; Budget Price: 1.25375; Capacitance: 7pF; Datasheet URL 1: http://www.eea.epson.com/portal/pls/portal/docs/1/1525528.PDF; Datasheet URL 2: http://www.eea.epson.com/portal/pls/portal/docs/1/1525451.PDF; Definied Quality: INDUSTRIAL; Esd Level: N/A; FPLIST: XTAL_FC-135N,XTAL_FC-135L,XTAL_FC-135M; Last Time Buy: N/A; Lead Time: 10; MPN: FC-135 32.7680KA-AG0; MPN Status: ACTIVE; MSL: N/A; MTBF: N/A; MTBF Standard: N/A; Manufacturer: EPSON; Max Oper Temp: +85DEGC; Max Tol: +20PPM; Min Oper Temp: -40DEGC; Min Tol: -20PPM; Mounting Type: SMD; NOTE Status: PREFERRED; Packing Size: 1000; Packing Type: TAPE_&_REEL; Part Number: 12-00546; Part Type: CRYSTAL\OSCILLATOR\MEMS; Revision: R001; RoHS Status: ROHS_COMPLIANT; WEIGHT: N/A
Y2 = XTAL_4PIN_S: CRYSTAL, CRYSTAL OSCILLATOR, 24MHz, -15PPM/DEGC/+15PPM/DEGC, -40DEGC/+85DEGC, SMD; ALT_SYMBOLS: OSCCC250X320X60-4L,OSCCC250X320X60-4M; AutoDoc File: http://notefied-dynamic-precision.com/DB/Apps/Desktop/Item/Object.aspx?id=96738; Budget Currency: EUR; Budget Price: 0.256; Capacitance: 9pF; Datasheet URL 1: http://www.eea.epson.com/portal/pls/portal/docs/1/1721495.PDF; Datasheet URL 2: http://www.epsondevice.com/docs/qd/en/DownloadServlet?id=ID000658; FPLIST: OSCCC250X320X60-4N,OSCCC250X320X60-4L,OSCCC250X320X60-4M; Lead Time: 12; MPN: TSX-3225 24.0000MF15X-AC3; MPN Status: ACTIVE; Manufacturer: EPSON; Max Oper Temp: +85DEGC; Max TC: +15PPM/DEGC; Max Tol: +10PPM; Min Oper Temp: -40DEGC; Min TC: -15PPM/DEGC; Min Tol: -10PPM; Mounting Type: SMD; NOTE Status: PREFERRED; Old Footprint: OSCCC250X320X60-4N; Packing Size: 250; Packing Type: TAPE_&_REEL; Part Number: 12-00757; Part Type: CRYSTAL\OSCILLATOR; Revision: R001; RoHS Status: ROHS_COMPLIANT

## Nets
GND: C1.2 C11.2 C12.2 C13.1 C14.1 C21.1 C41.2 C51.2 C131.2 C221.2 C231.2 C331.2 C341.2 C342.2 C351.2 C441.2 C451.2 C461.2 C471.2 C481.2 J1.2 J1.3 J1.4 J1.5 L15.2 L16.2 P1.1 P1.19 P2.2 P2.20 U1.49(VSS) Y2.2 Y2.4
VDD_EB: FL1.2 P2.7 P2.9
VDDR: C331.1 C451.1 C481.1 L331.2 U1.45(VDDR) U1.48(VDDR)
VDDS: C1.1 C131.1 C221.1 C341.1 C342.1 C441.1 FL1.1 R351.2 U1.13(VDDS2) U1.22(VDDS3) U1.34(VDDS_DCDC) U1.44(VDDS)
DCDC_SW: L331.1 U1.33(DCDC_SW)
DIO_1: P1.5 U1.6(DIO_1)
DIO_2: P1.7 U1.7(DIO_2)
DIO_3: P1.9 U1.8(DIO_3)
DIO_4: P1.11 U1.9(DIO_4)
DIO_5: P1.13 U1.10(DIO_5)
DIO_6: P1.4 U1.11(DIO_6)
DIO_7: P1.2 U1.12(DIO_7)
DIO_8: P1.20 U1.14(DIO_8)
DIO_9: P1.18 U1.15(DIO_9)
DIO_10: P1.16 U1.16(DIO_10)
DIO_11: P1.14 U1.17(DIO_11)
DIO_12: P1.12 U1.18(DIO_12)
DIO_13: P1.15 U1.19(DIO_13)
DIO_14: P1.17 U1.20(DIO_14)
DIO_15: P1.6 U1.21(DIO_15)
DIO_16 / JTAG TDO: P2.19 U1.26(DIO_16)
DIO_17 / JTAG TDI: P2.17 U1.27(DIO_17)
DIO_18: P1.8 U1.28(DIO_18)
DIO_19: P1.10 U1.29(DIO_19)
DIO_20: P2.8 U1.30(DIO_20)
DIO_21: P2.18 U1.31(DIO_21)
DIO_22: P1.3 U1.32(DIO_22)
DIO_23: P2.5 U1.36(DIO_23)
DIO_24: P2.10 U1.37(DIO_24)
DIO_25: P2.11 U1.38(DIO_25)
DIO_26: P2.6 U1.39(DIO_26)
DIO_27: P2.13 U1.40(DIO_27)
DIO_28: P2.16 U1.41(DIO_28)
DIO_29: P2.14 U1.42(DIO_29)
DIO_30: P2.12 U1.43(DIO_30)
JTAG_TCK: P2.1 U1.25(JTAG_TCKC)
JTAG_TMS: P2.4 U1.24(JTAG_TMSC)
nRESET: C351.1 P2.15 R351.1 U1.35(RESET_N)
N485531: C15.1 J1.1
N485535: A1.1(FEED/GND) L16.1 R13.1
N485571: C461.1 U1.46(X24M_N) Y2.3
N485643: C22.1 L11.2 L21.1 U1.2(RF_N)
N485645: C11.1 L11.1 L12.1 U1.1(RF_P)
N485661: C12.1 C22.2 L12.2 L13.1
N485675: C13.2 L13.2 L14.1
N485699: C231.1 U1.23(DCOUPL)
N485701: C41.1 U1.4(X32K_Q1) Y1.1
N485707: C51.1 U1.5(X32K_Q2) Y1.2
N485827: C14.2 C15.2 C16.2 L14.2
N485901: C16.1 L15.1 R13.2
N485927: C21.2 L21.2 U1.3(RX_TX)
N485953: C471.1 U1.47(X24M_P) Y2.1

Not connected (* = marked no-connect by the designer): FIDU1 1*; FIDU2 1*; FIDU3 1*; FIDU4 1*; FIDU5 1*; FIDU6 1*; P2 3*

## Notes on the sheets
sheet 1
- VDDS decoupling capacitors
- VDDR decoupling capacitors
- VDDS Decoupling Capacitors
- VDDR Decoupling Capacitors
- Pin 48
- Pin 13
- Pin 22
- Pin 44
- Pin 34
- Pin 45
- Place L331 and C331 close to pin 33.
  Low inductance ground for C331
- Mount either R11 or R12
  To select SMA or PCB ant.
- EM connector 1
- EM connector 2
sheet 2
- R 1.0.0
  --------------------------------------------------------------------------------------------
  -Initial release revision. Based on CC13xxEM-7XD-7793 R1.3.3
  R1.0.1
  ---------------------------------------------------------------------------------------------
  - L11 -> 27nH
  - C14 -> 3.0pF
  R1.1.0
  ---------------------------------------------------------------------------------------------
  C343 - Removed
  C482 - Removed
  Converting to 4 layer PCB based on CC13xxEM-7XD-7793_4L
